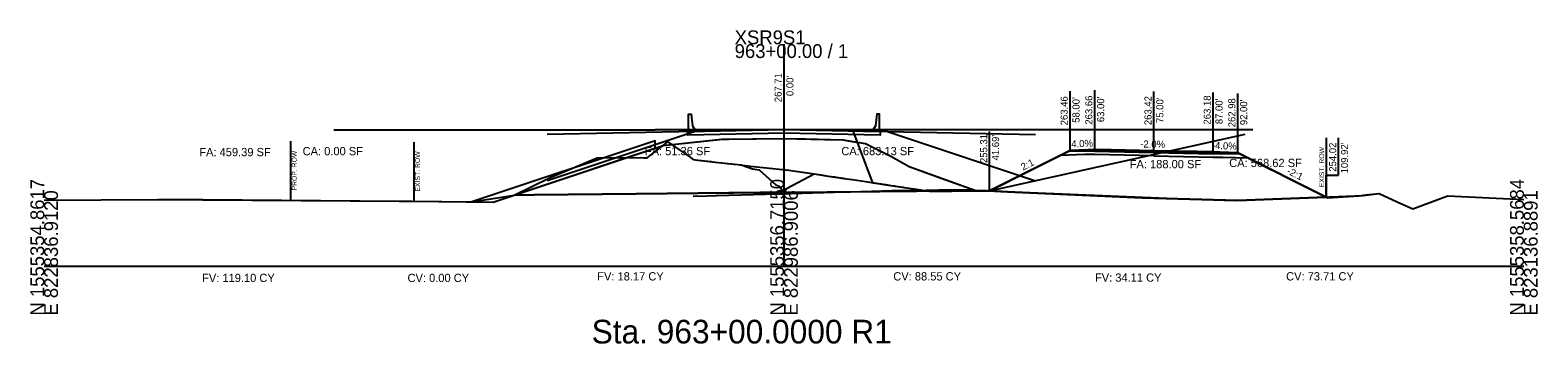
# Model space of a CAD drawing. Extents: x -26 to 823017, y -16 to 1558356.
# Drawn here: x 997.2 to 1302.8, y 2484.3 to 2547.8 of the extents above; entities that cross this region are included whole.
import ezdxf

# ---------------------------------------------------------------- set-up
doc = ezdxf.new("R2010")
doc.units = 0
for name, color, linetype in [('ASPHALT_19MM1', 7, 'Continuous'), ('CONST_DCH', 7, 'Continuous'), ('CONST_LV3', 7, 'Continuous'), ('Default', 7, 'Continuous'), ('Draft_XS_Grid', 7, 'Continuous'), ('Draft_XS_Text', 7, 'Continuous'), ('DTM_CORRIDOR', 7, 'Continuous'), ('DTM_P_FINISHED_GRADE2', 7, 'Continuous'), ('DTM_TEMP_DROP', 7, 'Continuous'), ('DTM_X_GROUND', 7, 'Continuous'), ('PROFILES_DCH_2', 7, 'Continuous'), ('SLOPE_STAKES_FILL', 7, 'Continuous'), ('XS_CELL', 7, 'Continuous'), ('XS_M_SHAPES_EARTHWORK', 7, 'Continuous'), ('XS_P_ASPHALT', 7, 'Continuous'), ('XS_P_CONCRETE', 7, 'Continuous'), ('XS_P_DR_GRAVEL', 7, 'Continuous'), ('XS_P_GROUND', 7, 'Continuous'), ('XS_P_NULL_POINT', 7, 'Continuous'), ('XS_P_ROW', 7, 'Continuous'), ('XS_P_SHOULDER', 7, 'Continuous'), ('XS_P_SUBGRADE_GRANULAR', 7, 'Continuous'), ('XS_P_SUBGRADE_UNDERCUT', 7, 'Continuous'), ('XS_P_TX_CLEARZONE', 7, 'Continuous'), ('XS_P_TX_FS_BS', 7, 'Continuous'), ('XS_SHEET_EW_TX_AREA', 7, 'Continuous'), ('XS_SHEET_EW_TX_VOLUME', 7, 'Continuous'), ('XS_X_ROW', 7, 'Continuous')]:
    doc.layers.add(name, color=color, linetype=linetype)

msp = doc.modelspace()

# ---------------------------------------------------------------- linework, layer by layer
at = {"layer": 'ASPHALT_19MM1'}
msp.add_lwpolyline([(1213, 2523.29), (1225, 2523.05), (1237, 2522.81), (1237, 2523.02), (1225, 2523.26), (1213, 2523.5), (1213, 2523.29)], dxfattribs=at)
at = {"layer": 'CONST_DCH'}
msp.add_lwpolyline([(1213, 2523.5), (1225, 2523.26), (1237, 2523.02), (1237, 2523.18), (1225, 2523.42), (1213, 2523.66), (1213, 2523.5)], dxfattribs=at)
at = {"layer": 'CONST_LV3'}
for points in [[(1058.7, 2527.66), (1063.68, 2527.66), (1069.05, 2527.66), (1075.04, 2527.66), (1079.41, 2527.66), (1086.41, 2527.66), (1089.76, 2527.66), (1092.56, 2527.66), (1100.11, 2527.66), (1102.06, 2527.66), (1110.46, 2527.66), (1120.52, 2527.66), (1120.82, 2527.66), (1123.88, 2527.66)], [(1102, 2526.75), (1132, 2527.35), (1150, 2527.71), (1171, 2527.29), (1201, 2526.69)], [(1102, 2517.35), (1132, 2527.35), (1150, 2527.71), (1171, 2527.29), (1201, 2517.29)], [(1123.88, 2527.7), (1124.29, 2527.7), (1133.24, 2527.7), (1140.68, 2527.7), (1143.19, 2527.7), (1152.97, 2527.7), (1162.51, 2527.7), (1163.95, 2527.7), (1170.51, 2527.7), (1180.75, 2527.7), (1181.83, 2527.7), (1196.07, 2527.7), (1201.15, 2527.7), (1204.2, 2527.7), (1207.78, 2527.7), (1220.23, 2527.7), (1220.47, 2527.7), (1239.18, 2527.71), (1239.79, 2527.71), (1245.05, 2527.71)], [(1150, 2527.71), (1164, 2527.43)], [(1168, 2516.93), (1168, 2516.93), (1164, 2527.43)], [(1191.69, 2515.31), (1191.69, 2515.31), (1243.53, 2526.77)], [(1191.69, 2515.31), (1196.23, 2517.58), (1208, 2523.46), (1211.62, 2523.61), (1213, 2523.66)], [(1191.69, 2515.31), (1195.49, 2517.21), (1196.35, 2517.64), (1196.78, 2517.85), (1197.8, 2518.36), (1208, 2523.46), (1209.55, 2523.52), (1213, 2523.66), (1221.28, 2523.5), (1225, 2523.42), (1228.72, 2523.35), (1237, 2523.18), (1238.55, 2523.12), (1242, 2522.98), (1247.36, 2520.3), (1250.52, 2518.73), (1260.22, 2513.87), (1266.59, 2514.28), (1267.4, 2514.38), (1267.99, 2514.45), (1270.65, 2514.72), (1274.31, 2513.08), (1277.49, 2511.66), (1283.08, 2513.75), (1284.56, 2514.29), (1300, 2513.56)], [(1242, 2522.98), (1259.92, 2514.02)], [(1000, 2513.38), (1023.07, 2513.53), (1031.18, 2513.5), (1031.46, 2513.5), (1032.19, 2513.5), (1071.98, 2513.19), (1072.05, 2513.19), (1072.18, 2513.19), (1072.21, 2513.19), (1072.24, 2513.19), (1072.78, 2513.18), (1074.51, 2513.17), (1086.73, 2513.06), (1086.73, 2513.06)]]:
    msp.add_lwpolyline(points, dxfattribs=at)
at = {"layer": 'Default'}
msp.add_lwpolyline([(1188.72, 2515.44), (1183.43, 2515.44), (1181.41, 2515.44), (1176.02, 2515.3), (1171.9, 2515.26), (1163.46, 2515.02), (1162.31, 2514.99), (1151.44, 2514.68), (1150.09, 2514.64), (1149.35, 2514.62), (1148.68, 2514.6), (1136.41, 2514.26), (1136.25, 2514.26), (1134.45, 2514.23), (1134.4, 2514.22), (1131.6, 2514.12)], dxfattribs=at)
at = {"layer": 'DTM_P_FINISHED_GRADE2'}
msp.add_lwpolyline([(1086.73, 2513.06), (1086.73, 2513.06), (1095.28, 2514.43), (1102.62, 2517.98), (1112.13, 2521.99), (1120.82, 2522.03), (1121.56, 2522), (1122.27, 2521.97), (1126.48, 2525.21), (1126.74, 2525.03), (1127.09, 2524.79), (1127.41, 2524.56), (1130.08, 2522.69), (1131.04, 2522.01), (1131.6, 2521.62), (1132.56, 2521.51), (1132.58, 2521.51), (1135.24, 2521.21), (1135.43, 2521.19), (1139.81, 2520.7), (1140.61, 2520.61), (1141.36, 2520.52), (1141.52, 2520.5), (1143.59, 2519.74), (1144.97, 2519.53), (1148.35, 2516.48), (1149.03, 2516.26), (1150, 2514.98), (1150.53, 2515.79), (1156.14, 2518.71), (1157.52, 2518.5), (1158.93, 2518.29), (1160.24, 2518.09), (1161.31, 2517.93), (1161.54, 2517.9), (1161.71, 2517.87), (1162.02, 2517.83), (1162.23, 2517.79), (1163.24, 2517.64), (1163.88, 2517.55), (1165.63, 2517.29), (1166.49, 2517.16), (1170.55, 2516.55), (1171.66, 2516.38), (1172.42, 2516.27), (1172.58, 2516.25), (1174.15, 2516.01), (1174.38, 2515.98), (1176.67, 2515.63), (1176.84, 2515.61), (1179.5, 2515.21), (1182.46, 2515.23), (1182.96, 2515.24), (1184.03, 2515.25), (1184.03, 2515.25), (1185.56, 2515.26), (1189.2, 2515.29), (1190.36, 2515.3), (1191.62, 2515.31), (1191.67, 2515.31), (1191.68, 2515.31), (1191.69, 2515.31)], dxfattribs=at)
at = {"layer": 'DTM_X_GROUND'}
for points in [[(1000, 2513.38), (1023.07, 2513.53), (1031.18, 2513.5), (1031.46, 2513.5), (1071.98, 2513.19), (1072.24, 2513.19), (1072.78, 2513.18), (1074.51, 2513.17), (1091.05, 2513.02), (1118.25, 2522.11), (1125.52, 2524.49), (1136.94, 2525.69), (1137.34, 2525.73), (1138.8, 2525.75), (1149.93, 2525.87), (1154.36, 2525.79), (1162, 2525.62), (1163.83, 2525.31), (1166.53, 2524.88), (1171.67, 2522.33), (1175.41, 2520.2), (1180.89, 2518.18), (1188.72, 2515.44), (1195.34, 2515.1), (1222.59, 2513.89), (1241.93, 2513.32), (1267.4, 2514.31), (1270.65, 2514.72), (1274.31, 2513.08), (1277.49, 2511.66), (1283.08, 2513.75), (1284.56, 2514.29), (1300, 2513.56)], [(1000, 2513.38), (1023.07, 2513.53), (1031.18, 2513.5), (1031.46, 2513.5), (1071.98, 2513.19), (1072.24, 2513.19), (1072.78, 2513.18), (1074.51, 2513.17), (1091.05, 2513.02), (1118.25, 2522.11), (1125.52, 2524.49), (1136.94, 2525.69), (1137.34, 2525.73), (1138.8, 2525.75), (1149.93, 2525.87), (1154.36, 2525.79), (1162, 2525.62), (1163.83, 2525.31), (1166.53, 2524.88), (1171.67, 2522.33), (1175.41, 2520.2), (1180.89, 2518.18), (1188.72, 2515.44), (1191.16, 2515.33), (1191.69, 2515.31), (1196.35, 2517.64), (1196.78, 2517.85), (1208, 2523.46), (1209.55, 2523.52), (1213, 2523.66), (1221.28, 2523.5), (1225, 2523.42), (1228.72, 2523.35), (1237, 2523.18), (1238.55, 2523.12), (1242, 2522.98), (1247.36, 2520.3), (1250.52, 2518.73), (1260.22, 2513.87), (1266.59, 2514.28), (1267.4, 2514.38), (1267.99, 2514.45), (1270.65, 2514.72), (1274.31, 2513.08), (1277.49, 2511.66), (1283.08, 2513.75), (1284.56, 2514.29), (1300, 2513.56)], [(1000, 2513.38), (1023.07, 2513.53), (1031.18, 2513.5), (1031.46, 2513.5), (1032.19, 2513.49), (1071.98, 2513.19), (1072.05, 2513.19), (1072.18, 2513.19), (1072.21, 2513.19), (1072.24, 2513.19), (1072.78, 2513.18), (1074.51, 2513.17), (1086.73, 2513.06), (1086.73, 2513.06), (1086.73, 2513.06), (1086.73, 2513.06), (1095.28, 2514.43), (1102.62, 2517.98), (1112.13, 2521.99), (1120.82, 2522.03), (1121.56, 2522), (1122.27, 2521.97), (1126.48, 2525.21), (1126.74, 2525.03), (1127.09, 2524.79), (1127.41, 2524.56), (1130.08, 2522.69), (1131.04, 2522.01), (1131.6, 2521.62), (1132.56, 2521.51), (1132.58, 2521.51), (1135.24, 2521.21), (1135.43, 2521.19), (1139.81, 2520.7), (1140.61, 2520.61), (1141.36, 2520.52), (1141.52, 2520.5), (1143.59, 2519.74), (1144.97, 2519.53), (1148.35, 2516.48), (1149.03, 2516.26), (1150, 2514.98), (1150.53, 2515.79), (1156.14, 2518.71), (1157.52, 2518.5), (1158.93, 2518.29), (1160.24, 2518.09), (1161.31, 2517.93), (1161.54, 2517.9), (1161.71, 2517.87), (1162.02, 2517.83), (1162.23, 2517.79), (1163.24, 2517.64), (1163.88, 2517.55), (1165.63, 2517.29), (1166.49, 2517.16), (1170.55, 2516.55), (1171.66, 2516.38), (1172.42, 2516.27), (1172.58, 2516.25), (1174.15, 2516.01), (1174.38, 2515.98), (1176.67, 2515.63), (1176.84, 2515.61), (1179.5, 2515.21), (1182.46, 2515.23), (1182.96, 2515.24), (1184.03, 2515.25), (1184.03, 2515.25), (1185.56, 2515.26), (1189.2, 2515.29), (1190.36, 2515.3), (1191.62, 2515.31), (1191.67, 2515.31), (1191.68, 2515.31), (1191.69, 2515.31), (1195.49, 2517.21), (1196.35, 2517.64), (1196.78, 2517.85), (1197.8, 2518.36), (1208, 2523.46), (1209.55, 2523.52), (1213, 2523.66), (1221.28, 2523.5), (1225, 2523.42), (1228.72, 2523.35), (1237, 2523.18), (1238.55, 2523.12), (1242, 2522.98), (1247.36, 2520.3), (1250.52, 2518.73), (1260.22, 2513.87), (1266.59, 2514.28), (1267.4, 2514.38), (1267.99, 2514.45), (1270.65, 2514.72), (1274.31, 2513.08), (1277.49, 2511.66), (1283.08, 2513.75), (1284.56, 2514.29), (1300, 2513.56)]]:
    msp.add_lwpolyline(points, dxfattribs=at)
at = {"layer": 'XS_CELL'}
for p, q in [((1150, 2500), (1150, 2545)), ((1000, 2500), (1150, 2500)), ((1150, 2500), (1300, 2500))]:
    msp.add_line(p, q, dxfattribs=at)
at = {"layer": 'XS_M_SHAPES_EARTHWORK'}
for points in [[(1086.73, 2513.06), (1091.05, 2513.02), (1118.25, 2522.11), (1123.88, 2523.95), (1123.88, 2525.44)], [(1095.28, 2514.43), (1118.25, 2522.11), (1125.52, 2524.49), (1136.94, 2525.69), (1137.34, 2525.73), (1138.8, 2525.75), (1149.93, 2525.87), (1154.36, 2525.79), (1162, 2525.62), (1163.83, 2525.31), (1166.53, 2524.88), (1171.67, 2522.33), (1175.41, 2520.2), (1180.89, 2518.18), (1188.72, 2515.44), (1191.36, 2515.3), (1184.87, 2515.25), (1150, 2514.98), (1145.1, 2514.93), (1120, 2514.68), (1099.35, 2514.47)], [(1191.36, 2515.3), (1191.69, 2515.29), (1191.69, 2515.31)]]:
    msp.add_lwpolyline(points, close=True, dxfattribs=at)
at = {"layer": 'XS_P_CONCRETE'}
for points in [[(1130.67, 2527.32), (1130.67, 2530.82), (1131.17, 2530.85), (1131.42, 2528.43), (1132, 2527.6), (1132, 2527.35), (1130.67, 2527.32)], [(1169.33, 2527.32), (1169.33, 2530.82), (1168.83, 2530.85), (1168.58, 2528.43), (1168, 2527.6), (1168, 2527.35), (1169.33, 2527.32)], [(1150, 2527.71), (1169.33, 2527.32), (1169.5, 2527.32), (1169.5, 2526.57), (1150, 2526.96), (1130.5, 2526.57), (1130.5, 2527.32), (1130.67, 2527.32), (1150, 2527.71)]]:
    msp.add_lwpolyline(points, dxfattribs=at)
at = {"layer": 'XS_P_DR_GRAVEL'}
for points in [[(1211.62, 2523.61), (1208, 2523.46), (1207.96, 2523.44), (1207.86, 2523.39), (1209.28, 2523.36), (1213, 2523.29), (1213, 2523.56), (1213, 2523.66), (1211.62, 2523.61)], [(1238.38, 2523.13), (1242, 2522.98), (1242.16, 2522.9), (1242.57, 2522.7), (1238.54, 2522.78), (1237, 2522.81), (1237, 2523.08), (1237, 2523.18), (1238.38, 2523.13)]]:
    msp.add_lwpolyline(points, dxfattribs=at)
at = {"layer": 'XS_P_GROUND'}
for points in [[(1208, 2523.46), (1191.69, 2515.31)], [(1242, 2522.98), (1260.28, 2513.84)], [(1131.6, 2521.62), (1132.58, 2521.51), (1135.43, 2521.19), (1140.61, 2520.61), (1141.52, 2520.5), (1143.24, 2520.31), (1145.78, 2520.03), (1150.96, 2519.45), (1151.88, 2519.34), (1156.14, 2518.71), (1158.93, 2518.29), (1161.31, 2517.93), (1161.71, 2517.87), (1162.23, 2517.79), (1163.88, 2517.55), (1166.49, 2517.16), (1170.27, 2516.59), (1171.66, 2516.38), (1172.58, 2516.25), (1174.38, 2515.98), (1176.84, 2515.61), (1179.5, 2515.21)], [(1168, 2516.93), (1168, 2516.93), (1168, 2516.93), (1170.55, 2516.55), (1170.55, 2516.55), (1171.66, 2516.38), (1172.42, 2516.27), (1172.42, 2516.27), (1172.58, 2516.25), (1174.15, 2516.01), (1174.38, 2515.98), (1176.67, 2515.63), (1176.67, 2515.63), (1176.67, 2515.63), (1176.67, 2515.63), (1176.84, 2515.61), (1176.84, 2515.61), (1179.5, 2515.21), (1179.5, 2515.21), (1179.5, 2515.21), (1179.5, 2515.21), (1182.46, 2515.23), (1182.46, 2515.23), (1182.96, 2515.24), (1184.03, 2515.25), (1184.03, 2515.25), (1185.56, 2515.26), (1185.56, 2515.26), (1189.2, 2515.29), (1189.2, 2515.29), (1190.36, 2515.3), (1190.36, 2515.3), (1191.62, 2515.31), (1191.62, 2515.31), (1191.67, 2515.31), (1191.68, 2515.31), (1191.69, 2515.31), (1191.69, 2515.31)], [(1168, 2516.93), (1168, 2516.93), (1168, 2516.93), (1168, 2516.93), (1170.55, 2516.55), (1170.55, 2516.55), (1170.55, 2516.55), (1171.66, 2516.38), (1172.42, 2516.27), (1172.42, 2516.27), (1172.58, 2516.25), (1174.15, 2516.01), (1174.38, 2515.98), (1176.67, 2515.63), (1176.67, 2515.63), (1176.67, 2515.63), (1176.67, 2515.63), (1176.84, 2515.61), (1176.84, 2515.61), (1179.5, 2515.21), (1179.5, 2515.21), (1179.5, 2515.21), (1179.5, 2515.21), (1182.46, 2515.23), (1182.46, 2515.23), (1182.46, 2515.23), (1182.96, 2515.24), (1184.03, 2515.25), (1184.03, 2515.25), (1185.56, 2515.26), (1185.56, 2515.26), (1189.2, 2515.29), (1189.2, 2515.29), (1190.36, 2515.3), (1190.36, 2515.3), (1191.62, 2515.3), (1191.62, 2515.3), (1191.67, 2515.31), (1191.68, 2515.31), (1191.69, 2515.31), (1191.69, 2515.31)], [(1095.28, 2514.43), (1099.35, 2514.47), (1120, 2514.68)], [(1120, 2514.68), (1145.1, 2514.93), (1150, 2514.98)], [(1191.69, 2515.31), (1184.87, 2515.25), (1150, 2514.98)], [(1259.92, 2514.02), (1241.93, 2513.32), (1241.93, 2513.32), (1222.59, 2513.89), (1222.59, 2513.89), (1195.34, 2515.1), (1195.34, 2515.1), (1191.69, 2515.29)], [(1191.69, 2515.29), (1195.34, 2515.1), (1195.34, 2515.1), (1222.59, 2513.89), (1222.59, 2513.89), (1241.93, 2513.32), (1241.93, 2513.32), (1259.92, 2514.02)]]:
    msp.add_lwpolyline(points, dxfattribs=at)
at = {"layer": 'XS_P_ROW'}
msp.add_line((1050, 2513.36), (1050, 2525.36), dxfattribs=at)
at = {"layer": 'XS_P_SHOULDER'}
for points in [[(1208, 2523.46), (1211.62, 2523.61), (1213, 2523.66)], [(1242, 2522.98), (1238.38, 2523.13), (1237, 2523.18)]]:
    msp.add_lwpolyline(points, dxfattribs=at)
at = {"layer": 'XS_P_SUBGRADE_GRANULAR'}
for points in [[(1213, 2522.62), (1211, 2522.66), (1206, 2522.46)], [(1225, 2522.38), (1213, 2522.62)], [(1225, 2522.38), (1237, 2522.14)], [(1237, 2522.14), (1239, 2522.1), (1243.96, 2522)]]:
    msp.add_lwpolyline(points, dxfattribs=at)
at = {"layer": 'XS_P_SUBGRADE_UNDERCUT'}
for points in [[(1095.28, 2514.43), (1125.52, 2524.49), (1137.34, 2525.73), (1149.93, 2525.87), (1158.18, 2525.7), (1162, 2525.62), (1166.53, 2524.88), (1171.67, 2522.33), (1175.41, 2520.2), (1188.72, 2515.44), (1191.69, 2515.31)], [(1191.69, 2515.31), (1232.53, 2513.6), (1241.54, 2513.33), (1259.92, 2514.02), (1242, 2522.98), (1238.38, 2523.13), (1233.68, 2523.25), (1225, 2523.42), (1216.32, 2523.6), (1213, 2523.66), (1211.62, 2523.61), (1208, 2523.46)]]:
    msp.add_lwpolyline(points, close=True, dxfattribs=at)
at = {"layer": 'XS_P_TX_CLEARZONE'}
for p, q in [((1150, 2527.71), (1150, 2539.71)), ((1208, 2523.46), (1208, 2535.46)), ((1213, 2523.66), (1213, 2535.66)), ((1225, 2523.42), (1225, 2535.42)), ((1237, 2523.18), (1237, 2535.18)), ((1242, 2522.98), (1242, 2534.98)), ((1191.69, 2515.31), (1191.69, 2527.31)), ((1191.69, 2515.29), (1191.69, 2527.29)), ((1262.44, 2518.44), (1262.44, 2526.02)), ((1259.92, 2514.02), (1259.92, 2518.44)), ((1259.92, 2518.44), (1262.44, 2518.44))]:
    msp.add_line(p, q, dxfattribs=at)
at = {"layer": 'XS_X_ROW'}
for p, q in [((1075, 2513.16), (1075, 2525.16)), ((1260, 2514.03), (1260, 2526.03))]:
    msp.add_line(p, q, dxfattribs=at)

# ---------------------------------------------------------------- texts
at = {"layer": 'CONST_DCH'}
for p in [(1191.61, 2515.19), (1259.84, 2513.9), (1260.2, 2513.72)]:
    msp.add_text('X', height=0.24, dxfattribs=at).set_placement(p)
at = {"layer": 'Draft_XS_Grid'}
msp.add_text('-', height=0.0001, dxfattribs=at).set_placement((1000, 2500))
at = {"layer": 'Draft_XS_Text'}
msp.add_text('Sta. 963+00.0000 R1', height=4.8, dxfattribs=at).set_placement((1111, 2484.35))
at = {"layer": 'DTM_CORRIDOR'}
for p in [(1212.92, 2523.54), (1224.92, 2523.3), (1236.92, 2523.06)]:
    msp.add_text('X', height=0.24, dxfattribs=at).set_placement(p)
at = {"layer": 'DTM_TEMP_DROP'}
for p in [(1149.92, 2527.59), (1131.52, 2521.5), (1191.61, 2515.17)]:
    msp.add_text('X', height=0.24, dxfattribs=at).set_placement(p)
at = {"layer": 'PROFILES_DCH_2'}
for p in [(1167.92, 2516.81), (1191.61, 2515.19), (1259.84, 2513.9)]:
    msp.add_text('X', height=0.24, dxfattribs=at).set_placement(p)
at = {"layer": 'SLOPE_STAKES_FILL'}
for p in [(1086.65, 2512.94), (1095.2, 2514.31), (1149.92, 2514.86), (1179.42, 2515.09), (1191.61, 2515.19)]:
    msp.add_text('X', height=0.24, dxfattribs=at).set_placement(p)
at = {"layer": 'XS_CELL'}
for s, p in [('XSR9S1', (1140, 2545)), ('963+00.00 / 1', (1140, 2542.2))]:
    msp.add_text(s, height=2.8, dxfattribs=at).set_placement(p)
for s, p in [('N 1555354.8617', (1000, 2490)), ('N 1555356.7150', (1150, 2490)), ('N 1555358.5684', (1300, 2490)), ('E 822836.9120', (1002.8, 2490)), ('E 822986.9006', (1152.8, 2490)), ('E 823136.8891', (1302.8, 2490))]:
    msp.add_text(s, height=2.8, rotation=90, dxfattribs=at).set_placement(p)
at = {"layer": 'XS_P_ASPHALT'}
for p in [(1191.61, 2515.19), (1260.2, 2513.72)]:
    msp.add_text('X', height=0.24, dxfattribs=at).set_placement(p)
at = {"layer": 'XS_P_NULL_POINT'}
for p in [(1086.65, 2512.94), (1191.61, 2515.19)]:
    msp.add_text('X', height=0.24, dxfattribs=at).set_placement(p)
at = {"layer": 'XS_P_ROW'}
msp.add_text('PROP. ROW', height=1, rotation=90, dxfattribs=at).set_placement((1051.2, 2515.36))
at = {"layer": 'XS_P_SHOULDER'}
for p in [(1207.92, 2523.34), (1241.92, 2522.86), (1149.92, 2514.86)]:
    msp.add_text('X', height=0.24, dxfattribs=at).set_placement(p)
at = {"layer": 'XS_P_TX_CLEARZONE'}
for s, p in [('267.71', (1149.52, 2533.25)), ("0.00'", (1151.92, 2534.49)), ('263.46', (1207.52, 2528.56)), ("58.00'", (1209.92, 2529.07)), ('263.66', (1212.52, 2528.69)), ("63.00'", (1214.92, 2529.2)), ('263.42', (1224.52, 2528.6)), ("75.00'", (1226.92, 2529.03)), ('263.18', (1236.52, 2528.72)), ("87.00'", (1238.92, 2528.79)), ('262.98', (1241.52, 2528.16)), ("92.00'", (1243.92, 2528.59)), ('255.31', (1191.21, 2520.92)), ("41.69'", (1193.61, 2521.44)), ('254.02', (1261.96, 2519.16)), ("109.92'", (1264.36, 2518.82))]:
    msp.add_text(s, height=1.44, rotation=90, dxfattribs=at).set_placement(p)
at = {"layer": 'XS_P_TX_FS_BS'}
for s, rotation, p in [('4.0%', 2.2906, (1208.27, 2524.07)), ('-2.0%', 358.8542, (1222.22, 2524.08)), ('-4.0%', 357.7094, (1236.73, 2523.79)), ('2:1', 26.565, (1198.48, 2519.37)), ('-2:1', 333.4349, (1251.81, 2518.84))]:
    msp.add_text(s, height=1.44, rotation=rotation, dxfattribs=at).set_placement(p)
at = {"layer": 'XS_SHEET_EW_TX_AREA'}
for s, p in [('FA: 459.39 SF', (1031.45, 2522.3)), ('CA: 0.00 SF', (1052.4, 2522.49)), ('FA: 51.36 SF', (1121.79, 2522.5)), ('CA: 683.13 SF', (1161.62, 2522.5)), ('FA: 188.00 SF', (1220.09, 2519.86)), ('CA: 568.62 SF', (1240.26, 2520.1))]:
    msp.add_text(s, height=1.68, dxfattribs=at).set_placement(p)
at = {"layer": 'XS_SHEET_EW_TX_VOLUME'}
for s, p in [('FV: 119.10 CY', (1032.02, 2496.8)), ('CV: 0.00 CY', (1073.67, 2496.8)), ('FV: 18.17 CY', (1112.13, 2497.12)), ('CV: 88.55 CY', (1172.16, 2497.12)), ('FV: 34.11 CY', (1213.05, 2496.87)), ('CV: 73.71 CY', (1251.8, 2497.12))]:
    msp.add_text(s, height=1.68, dxfattribs=at).set_placement(p)
at = {"layer": 'XS_X_ROW'}
for p in [(1076.2, 2515.16), (1259.51, 2516.03)]:
    msp.add_text('EXIST. ROW', height=1, rotation=90, dxfattribs=at).set_placement(p)

doc.saveas('drawing.dxf')
